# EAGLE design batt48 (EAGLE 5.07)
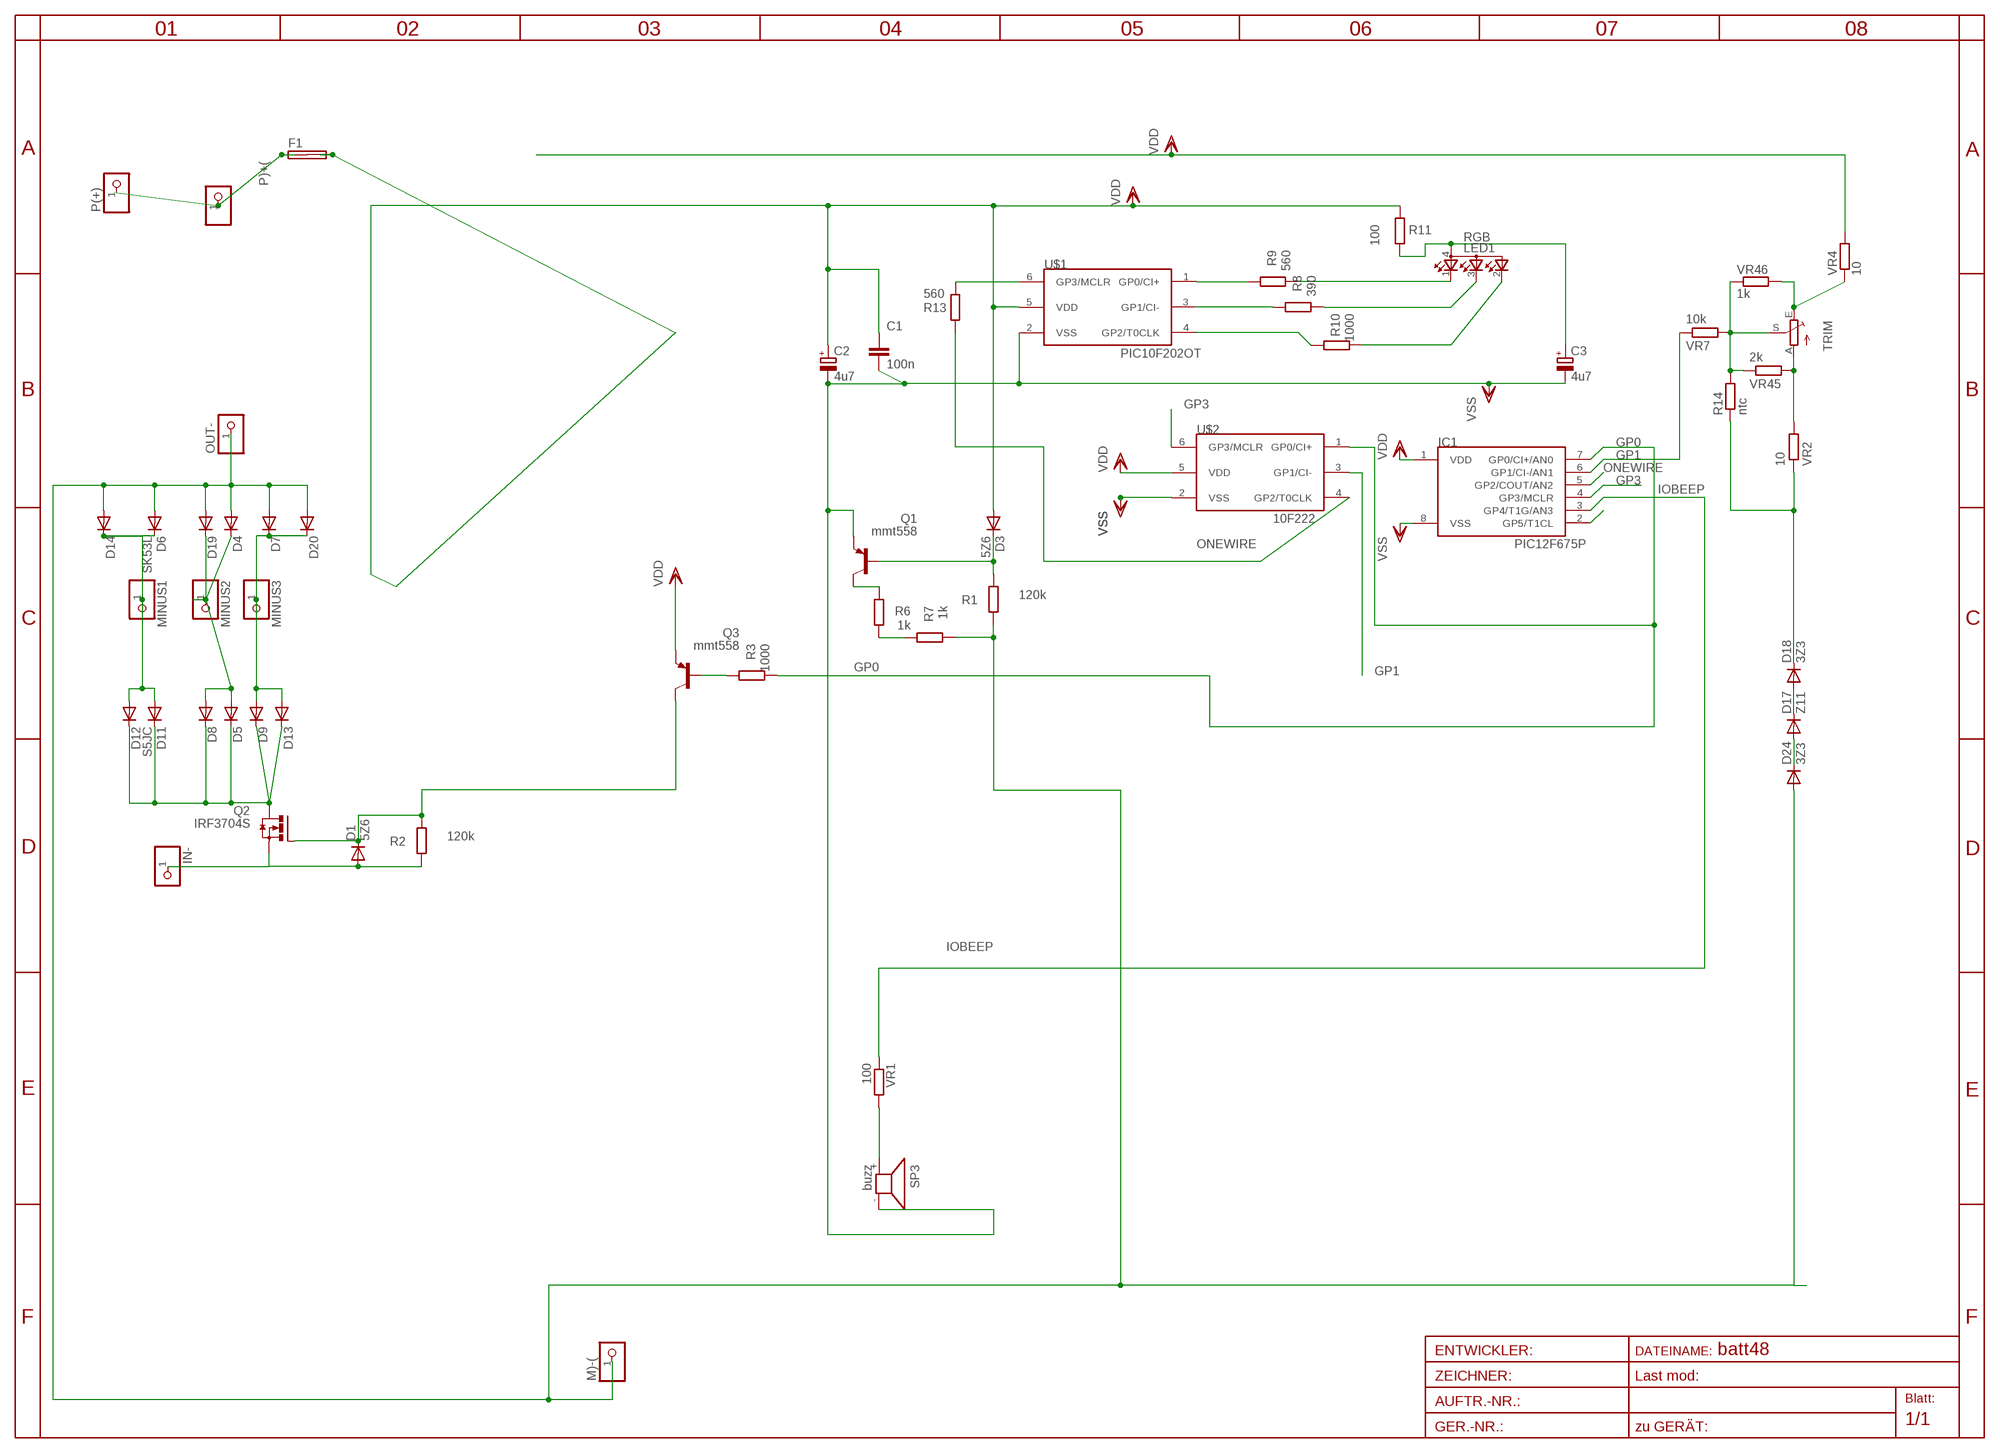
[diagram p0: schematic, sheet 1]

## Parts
C1  100n  C-EUC1206  [C1206]
C2  4u7  CPOL-EUSMCA  [SMC_A]
C3  4u7  CPOL-EUSMCA  [SMC_A]
D1  5Z6  DIODE-MINIMELF  [MINIMELF]
D3  5Z6  DIODE-MINIMELF  [MINIMELF]
D4  DIODE-SMC  [SMC]
D5  DIODE-SMC  [SMC]
D6  SK53L  DIODE-SMC  [SMC]
D7  DIODE-SMC  [SMC]
D8  DIODE-SMC  [SMC]
D9  DIODE-SMC  [SMC]
D11  S5JC  DIODE-SMC  [SMC]
D12  DIODE-SMC  [SMC]
D13  DIODE-SMC  [SMC]
D14  DIODE-SMC  [SMC]
D17  Z11  DIODE-MINIMELF  [MINIMELF]
D18  3Z3  DIODE-MINIMELF  [MINIMELF]
D19  DIODE-SMC  [SMC]
D20  DIODE-SMC  [SMC]
D24  3Z3  DIODE-MINIMELF  [MINIMELF]
F1  SHK20L7MM5  [7MM5]
IC1  PIC12F675P  [DIL8]
IN-  PINHD-1X12MM3  [1X2MM3]
LED1  RGB  GM1WA55311A  [FULL3528]
M)-(  PINHD-1X11X0.4  [1X01]
MINUS1  PINHD-1X12MM3  [1X2MM3]
MINUS2  PINHD-1X12MM3  [1X2MM3]
MINUS3  PINHD-1X12MM3  [1X2MM3]
OUT-  PINHD-1X12MM3  [1X2MM3]
P(+)  PINHD-1X14.5MM  [1X4MM5]
P)+(  PINHD-1X11X0.4  [1X01]
Q1  mmt558  BC857ALT1SMD  [SOT23-BEC]
Q2  IRF3704S  [D2PACK]
Q3  mmt558  BC857ALT1SMD  [SOT23-BEC]
R1  120k  R-EU_R1206  [R1206]
R2  120k  R-EU_R0805  [R0805]
R3  1000  R-EU_R0805  [R0805]
R6  1k  R-EU_R1206  [R1206]
R7  1k  R-EU_R1206  [R1206]
R8  390  R-EU_R0805  [R0805]
R9  560  R-EU_R0805  [R0805]
R10  1000  R-EU_R0805  [R0805]
R11  100  R-EU_R1206  [R1206]
R13  560  R-EU_R0805  [R0805]
R14  ntc  R-EU_0204/5  [0204/5]
SP3  buzz  KSS12017MM  [KSS1202]
TRIM  TRIM_EU-S64W  [S64W]
U$1  PIC10F202OT  [SOT23-6]
U$2  10F222  PIC10F204OT  [SOT23-6]
VR1  100  R-EU_R0805  [R0805]
VR2  10  R-EU_R0805  [R0805]
VR4  10  R-EU_R1206  [R1206]
VR7  10k  R-EU_R0805  [R0805]
VR45  2k  R-EU_R0805  [R0805]
VR46  1k  R-EU_R0805  [R0805]

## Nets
A: C3.+ LED1.4(A) R11.1
B: LED1.3(CBLUE) R8.1
B1: D6.C D11.A D12.A D14.C MINUS1.1
B2: D7.C D9.A D13.A D20.C MINUS3.1
B3: D4.C D5.A D8.A D19.C MINUS2.1
BUZZ+: SP3.+ VR1.2
G: LED1.2(CGREEN) R10.1
GP0: IC1.7(GP0/CI+/AN0) R3.1 U$2.1(GP0/CI+)
GP0C: R9.2 U$1.1(GP0/CI+)
GP1: IC1.6(GP1/CI-/AN1) U$2.3(GP1/CI-) VR7.1
GP1C: R8.2 U$1.3(GP1/CI-)
GP2C: R10.2 U$1.4(GP2/T0CLK)
GP3: IC1.4(GP3/MCLR) U$2.6(GP3/MCLR)
GP3_2: R13.1 U$1.6(GP3/MCLR)
IN+: F1.1A F1.1B P(+).1 P)+(.1
IN-: D5.C D8.C D9.C D11.C D12.C D13.C Q2.2(D)
IOBEEP: IC1.3(GP4/T1G/AN3) VR1.1
N$1: D1.A IN-.1 Q2.3(S) R2.2
N$2: D3.C Q1.B R1.1
N$4: D1.C Q2.1(G) Q3.C R2.1
N$5: D18.C R14.1 VR2.1
N$6: Q1.C R6.2
N$7: TRIM.A VR2.2 VR45.2
N$8: Q3.B R3.2
N$12: D17.C D18.A
N$14: D17.A D24.C
N$18: R6.1 R7.2
N$22: R14.2 TRIM.S VR7.2 VR45.1 VR46.1
N$24: TRIM.E VR4.1 VR46.2
N$38: IC1.2(GP5/T1CL)
ONEWIRE: IC1.5(GP2/COUT/AN2) R13.2 U$2.4(GP2/T0CLK)
OUT-: D4.A D6.A D7.A D14.A D19.A D20.A D24.A M)-(.1 OUT-.1 R1.2 R7.1
R: LED1.1(CRED) R9.1
VDD: C1.1 C2.+ D3.A F1.2A F1.2B IC1.1(VDD) Q3.E R11.2 U$1.5(VDD) U$2.5(VDD) VR4.2
VSS: C1.2 C2.- C3.- IC1.8(VSS) Q1.E SP3.- U$1.2(VSS) U$2.2(VSS)

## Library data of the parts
C1 = rcl:C-EU: CAPACITOR, European symbol
C2 C3 = rcl:CPOL-EU: POLARIZED CAPACITOR, European symbol
D1 D3-D9 D11-D14 D17-D20 D24 = diode:DIODE-: DIODE
F1 = fuse:SHK20L: FUSE HOLDER 5 x 20 mm, SH contact, SHH1 Schukat, E1073 Buerklin
IC1 = microchip-3:PIC12F6*: uPC nW 1k Program Flash memory 2x Timer Comparator 10b A/D converter/ 4xIN
IN- M)-( MINUS1-MINUS3 OUT- P(+) P)+( = pinhead:PINHD-1X1: PIN HEADER
LED1 = led:GM1WA55311A: Chip LED RGB Source: http://document.sharpsma.com/files/GM1WA55311A_SS.pdf
Q1 Q3 = transistor-pnp:BC857*: PNP Transistror
Q2 = transistor-power:IRF3704: SMPS MOSFET HEXFET® Power MOSFET Source: http://www.irf.com/product-info/datasheets/data/irf3704.pdf
R1-R3 R6-R11 R13 VR1 VR2 VR4 VR7 VR45 VR46 = rcl-2:R-EU_: RESISTOR, European symbol
R14 = rcl:R-EU_: RESISTOR, European symbol
SP3 = buzzer:KSS1201: SPEAKER
TRIM = pot:TRIM_EU-: POTENTIOMETER
U$1 U$2 = microchip-3:PIC10F2*: uPC nW 0,25/0,5k Program Flash memory Comparator

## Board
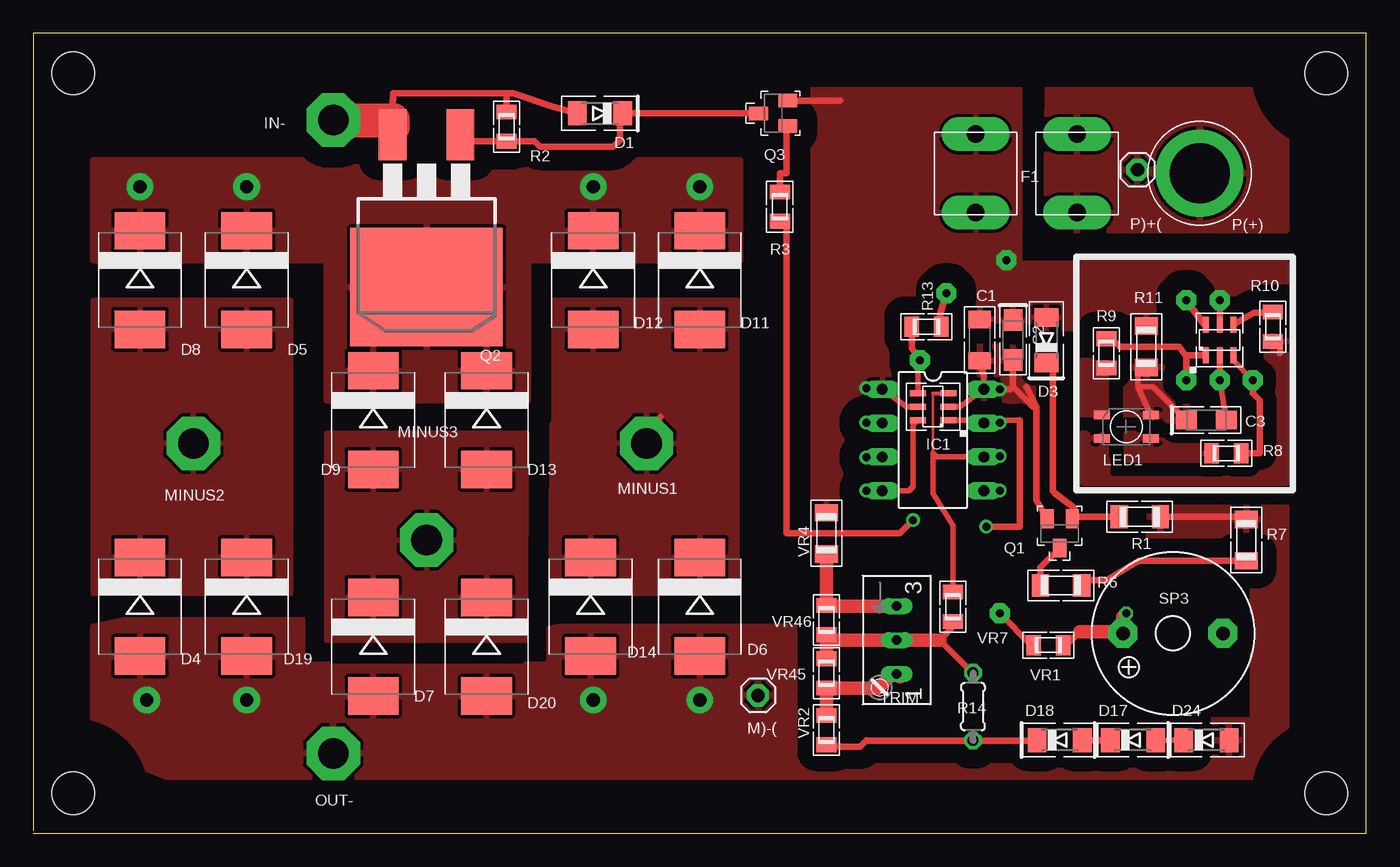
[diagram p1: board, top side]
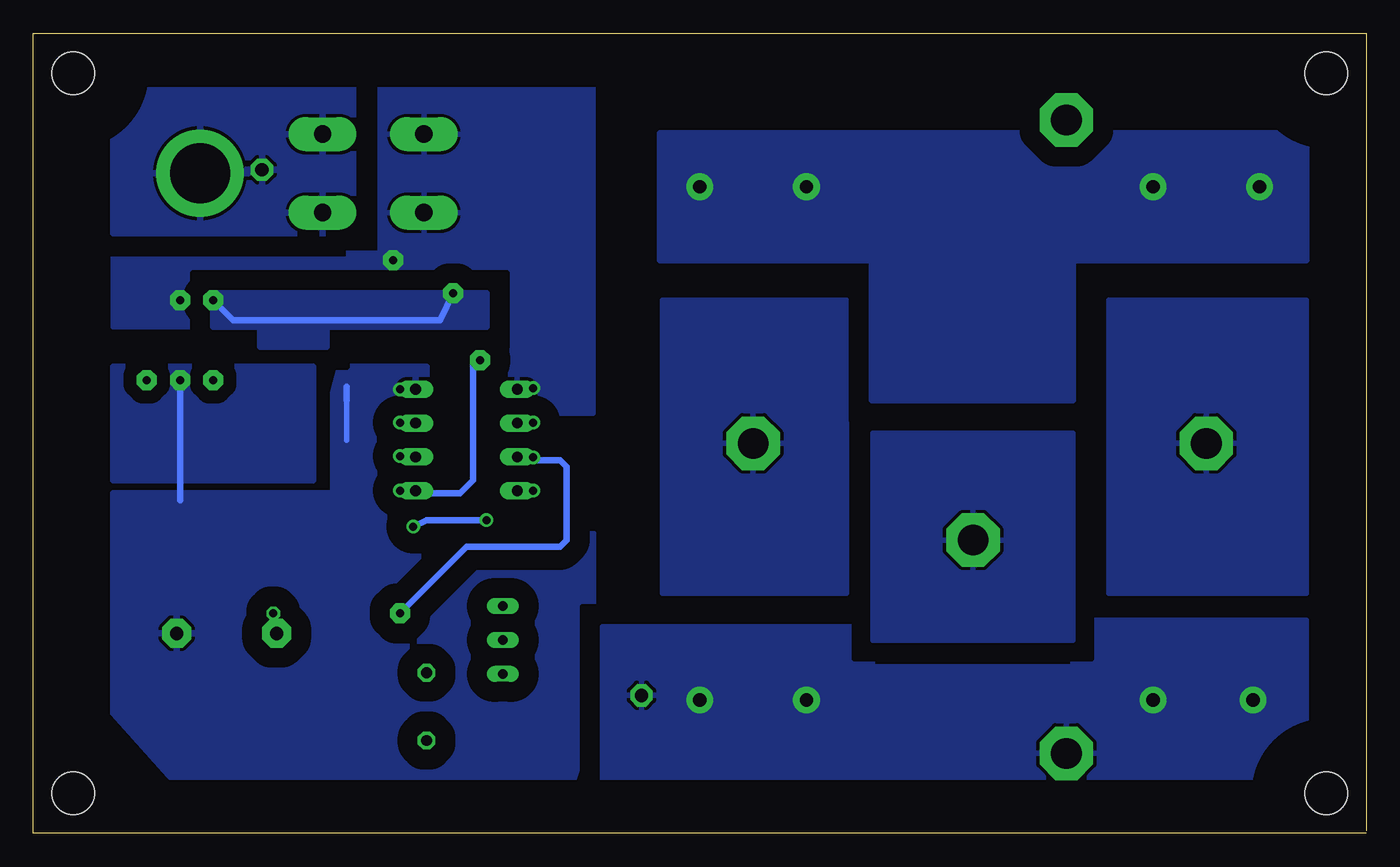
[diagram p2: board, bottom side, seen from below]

Size 100 x 60 mm. Coordinates in mm from the lower left corner, seen from the top.
Outline: 0,0 100,0 100,60 0,60 0,0.2
Copper layers (1*16): Top 0.035mm / dielectric 1.5mm / Bottom 0.035mm
Design rules "default *": minimum track width 8mil, minimum drill 4mil, track to track 8mil, track to pad 8mil, pad to pad 8mil, via to via 8mil, smd to smd 8mil, copper to edge 4mm, drill to drill 8mil, minimum pad ring 10mil, minimum via ring 8mil, stop-mask expansion 4mil, vias tented up to drill 0mil, thermal gap 10mil
Holes 3.2 mm at 3,57 3,3 97,57 97,3

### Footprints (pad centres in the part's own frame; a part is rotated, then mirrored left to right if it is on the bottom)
C1206 = smd 1.3 x 1.7: 1 -1.55,0; 2 1.55,0
SMC_A = smd 1.6 x 1.4: + -1.5,0; - 1.5,0
MINIMELF = smd 1.4 x 1.8: A 1.7,0; C -1.7,0
SMC = smd 2.8 x 3.8: A 3.7,0; C -3.7,0
7MM5 = drill 1.3 pad 2.54 long: 1A -3.8,2.94; 1B -3.8,-2.94; 2A 3.8,2.94; 2B 3.8,-2.94
DIL8 = drill 0.813 long: 1 -3.81,-3.81; 2 -1.27,-3.81; 3 1.27,-3.81; 4 3.81,-3.81; 5 3.81,3.81; 6 1.27,3.81; 7 -1.27,3.81; 8 -3.81,3.81
1X2MM3 = drill 2.3 pad 4 octagon: 1 0,0
FULL3528 = smd 0.65 x 1.2: 1 0.875,1.85; 2 -0.875,1.85; 3 -0.875,-1.85; 4 0.875,-1.85
1X01 = drill 1 pad 1.676 octagon: 1 0,0
1X4MM5 = drill 4.5 pad 6.35 round: 1 0,0
SOT23-BEC = smd 1 x 1.4: B -0.95,-1.1; C 0,1.1; E 0.95,-1.1
D2PACK = smd 2.083 x 3.81: 1 -2.54,-8.89; 3 2.54,-8.89 | smd 11.43 x 8.89: 2 0,2.54
R1206 = smd 1.3 x 1.7: 1 -1.55,0; 2 1.55,0
R0805 = smd 1.1 x 1.5: 1 -1.1,0; 2 1.1,0
0204/5 = drill 0.813 octagon: 1 -2.54,0; 2 2.54,0
KSS1202 = drill 1 pad 2.159 octagon: + 3.75,0; - -3.75,0
S64W = drill 0.7 long: A 2.54,1.27; E -2.54,1.27; S 0,1.27
SOT23-6 = smd 0.45 x 1.2: 1 -1.016,-1.15; 2 0,-1.15; 3 1.016,-1.15; 4 1.016,1.15; 5 0,1.15; 6 -1.016,1.15

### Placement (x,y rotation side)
C1  71,37 270 top
C2  73.5,37 270 top
C3  88,31 0 top
D1  42.5,54 180 top
D3  76,37 90 top
D4  8,17 270 top
D5  16,41.5 270 top
D6  50,17 270 top
D7  25.5,14 270 top
D8  8,41.5 270 top
D9  25.5,31 270 top
D11  50,41.5 270 top
D12  42,41.5 270 top
D13  34,31 270 top
D14  41.8,17 270 top
D17  82.5,7 0 top
D18  77,7 0 top
D19  16,17 270 top
D20  34,14 270 top
D24  88,7 0 top
F1  74.5,49.5 180 top
IC1  67.5,29.5 270 top
IN-  22.5,53.5 180 top
LED1  82,30.5 90 top
M)-(  54.37,10.35 0 top
MINUS1  46,29.25 180 top
MINUS2  12,29.25 180 top
MINUS3  29.5,22 180 top
OUT-  22.5,6 180 top
P(+)  87.5,49.5 0 top
P)+(  82.84,49.77 0 top
Q1  77,22.5 180 top
Q2  29.5,43.5 180 top
Q3  55.5,54 90 top
R1  83,23.75 0 top
R2  35.5,53 90 top
R3  56,47 90 top
R6  77.1,18.6 180 top
R7  91,22 270 top
R8  89.5,28.5 0 top
R9  80.5,36 90 top
R10  93,38 90 top
R11  83.5,36.5 90 top
R13  67,38 180 top
R14  70.5,9.5 90 top
SP3  85.5,15 180 top
TRIM  63.5,14.5 270 top
U$1  89,37 0 top
U$2  67.5,32 90 top
VR1  76.16,14.11 0 top
VR2  59.5,7.75 90 top
VR4  59.5,22.5 90 top
VR7  69,17 270 top
VR45  59.5,12 270 top
VR46  59.5,16 90 top

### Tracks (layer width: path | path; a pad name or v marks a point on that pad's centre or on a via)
A
  Top 0.4: 82.85,33.5 82.85,34.8 R11.1 | LED1.4 82.85,33.5 | C3.+ 84,33.5 82.85,33.5
  pour Top (isolate 1, rank 2): 82,35.5 87,35.5 87,31 82,31
B
  pour Top (isolate 1.016): 82,30 83.5,30 84,29.5 88,29.5 88,28 82,28
B1
  Top 0.5: MINUS1.1 47.05,31.25
  pour Top (isolate 1.5, rank 4): 52.8,18 38.8,18 38.8,40 52.8,40
  pour Bottom (isolate 1.5, rank 4): 52.8,18 39,18 39,40 52.8,40
B2
  pour Top (isolate 1.5, rank 3): 22,14.5 22,30 37,30 36.9,14.5
  pour Bottom (isolate 1.5, rank 3): 22,14.5 22,30 37,30 37,14.5
B3
  pour Top (isolate 1.5, rank 4): 4.5,18 4.5,40 19.3,40 19.3,18
  pour Bottom (isolate 1.5, rank 4): 4.5,18 4.5,40 19.3,40 19.3,18
BUZZ+  (via drill 0.6)
  Top 0.406: 81.75,16.25 v82,16.5 81.39,15.11
  Top 0.5: VR1.2 77.5,14.11 78.5,15.11
  Top 1: 81.75,16.25 SP3.+ | 78.5,15.11 81.39,15.11
G
  Top 0.5: R10.1 93.5,36.9 93.5,36
  pour Top (isolate 1, rank 2): 78.75,30 80.5,30 80.5,28 92.5,28 92.5,37.5 94,37.5 94,26.25 78.75,26.25
GP0  (via drill 0.6 pad 0.81, 0.6 pad 1)
  Top 0.4: U$2.1 71.1,30.98 IC1.7
  Top 0.406: 74,31 71.5,31 71.31,30.81 IC1.7 71.34,30.8 v72.5,30.8
  Top 0.5: R3.1 56.5,45.9 56.5,22.5 65,22.5 v66,23.5 | v71.5,23 74,23 74,31
  Bottom 0.5: v66,23.5 70.5,23.5 v71.5,23
GP0C  (via drill 0.6 pad 1.5)
  Top 0.4: R9.2 80.9,37.1 81.5,36.5
  Top 0.5: 86.5,35.75 v86.5,34 | 81.5,36.5 85.97,36.5 86.5,35.75 | U$1.1 86.6,35.85 86.5,35.75
GP1  (via drill 0.6 pad 1)
  Top 0.2: 67.5,28.5 67.5,33
  Top 0.3: 67.5,33 68.63,33
  Top 0.4: IC1.6 67.77,28.23 67.5,28.5 67.5,25.5 69,23.1
  Top 0.406: VR7.1 69,23.1 | IC1.6 72.43,28.23 v72.5,28.3 | 68.63,33 U$2.3
GP1C  (via drill 0.6 pad 1.5)
  Top 0.4: U$1.3 90.02,35.48 v91.5,34
  Top 0.5: v91.5,34 91.5,33 92,32.5 92,28.5 R8.2
GP2C
  Top 0.5: U$1.4 91.55,39.05 93,39.05 R10.2
GP3  (via drill 0.6 pad 1)
  Top 0.4: IC1.4 65.69,25.69 66,26 66,30.63 U$2.6
  Top 0.406: IC1.4 v62.51,25.69 v62.5,25.7
GP3_2  (via drill 0.6 pad 1.5)
  Top 0.5: U$1.6 87.85,38.15 v86.5,40 | v68.5,40.5 68,38.9 R13.1
  Bottom 0.5: v86.5,40 85,38.5 69.5,38.5 v68.5,40.5
  pour Bottom (isolate 1): 66,40.5 86.5,40.5 86.5,38 83,38 83,36.5 78,36.5 78,38 66,38
IN+
  pour Top (isolate 1.5): 76.1,56 94,56 94,45.25 77,45.25 76,46
  pour Bottom (isolate 1.5): 76,56 94,56 94,45 77,45 76,46
IN-  (via drill 1 pad 2)
  other vias: 8,48.5 16,48.5 42,48.5 50,48.5
  pour Top (isolate 1.5): 4.5,50.5 53,50.5 53,43 37.1,43 37.1,32.5 22,32.5 22,43 4.5,43
  pour Bottom (isolate 1.5): 4.5,52.5 53,52.5 53,43 37.1,43 37.1,32.5 22,32.5 22,43 4.5,43
IOBEEP  (via drill 0.6 pad 1, 0.6 pad 1.5)
  Top 0.406: v62.5,28.2 62.7,28
  Top 0.5: VR1.1 74.89,14.11 v72.5,16.5
  Bottom 0.406: v72.5,16.5 72,16.5 | 63.46,28 IC1.3
  Bottom 0.5: 62.5,28 60.5,28 60,27.5 60,22 60.5,21.5 67.5,21.5 v72.5,16.5 | 62.5,28 63.46,28 | 62.5,28 v62.5,28.2
N$1
  Top 0.5: D1.A 39,54.5 36,55.5 35.5,55.5 | 35.5,55.5 27,55.5 27,55 26.96,55 26.96,53 Q2.3 | 35.5,55.5 R2.2
  Top 2.54: IN-.1 26.96,53.5 26.96,53
N$2
  Top 0.5: D3.C 76.22,35.28 76.5,35 76.5,25.65 76.65,25.5 78,24.5 78.1,24.4 78.1,23.75 | 78.1,23.75 R1.1 | Q1.B 78.1,23.75
N$3  (via drill 0.6 pad 1)
  other vias: 72.5,25.7
N$4
  Top 0.5: Q3.C D1.C 44,53.8 44,52 43.5,51.5 38,51.5 37.6,51.9 R2.1 32.9,51.9 32.5,51.5 32,51.5 Q2.1
N$5
  Top 0.5: VR2.1 60.6,6.5 62,6.5 62.5,7 62.5,6.96 R14.1 75.26,6.96 D18.C
N$6
  Top 0.5: R6.2 75.55,19.95 Q1.C
N$7
  Top 0.406: 65,11.73 TRIM.A
  Top 0.5: VR2.2 60,9 59.5,9
  Top 1: 65,11.73 64.5,12 63.4,10.9 VR45.2 59.5,9
N$8
  Top 0.5: Q3.B 56.5,53.05 56.5,49.5 56,49.5 R3.2
N$12
  Top 0.5: D18.A D17.C
N$14
  Top 0.406: D24.C D17.A
N$18
  Top 0.5: R7.2 82.95,20.45 80.5,19 79.05,19 R6.1
N$22
  Top 0.406: 69,15.5 VR7.2
  Top 0.5: 69,15.5 68,14.5 70.46,12.04 R14.2
  Top 1: VR46.1 59.5,14.5 | VR45.1 59.5,14 59.5,14.5 | 68,14.5 TRIM.S 59.5,14.5
N$24
  Top 0.406: VR46.2 59.94,17.04
  Top 1: 59.94,17.04 TRIM.E | VR46.2 VR4.1
N$29  (via drill 0.6 pad 1)
  other vias: 62.5,30.8
ONEWIRE  (via drill 0.6 pad 1.5)
  Top 0.4: U$2.4 66.35,34.5 66.35,34.85
  Top 0.406: v66.5,35.5 66.35,35.85 66.35,34.5
  Top 0.5: R13.2 65.9,36.4 v66.5,35.5
  Bottom 0.406: 67,35.5 v66.5,35.5 | 71.12,25.5 IC1.5
  Bottom 0.5: 71.12,25.5 68,25.5 67,26.5 67,35.5
OUT-  (via drill 1 pad 2)
  Top 0.406: 91,23.75 R7.1
  Top 0.5: R1.2 91,23.75
  other vias: 50,10 42,10 16,10 8.5,10
  pour Top (isolate 1.422, rank 5): 94,3.5 11.8,3.5 4.5,6.5 4.5,15.5 6.8,16 21.5,16 22,12.5 37,12.5 37,15 39.5,15.5 69,15.5 69,8.5 91.5,8.5 91.5,21 83.5,21 83.5,24.5 94,24.5
  pour Bottom (isolate 1.422, rank 4): 57.3,4 8.3,3.5 4.5,6.5 4.5,16 22,16 22,12.5 37,12.5 37.5,15.5 57.3,15.5
R
  pour Top (isolate 1, rank 3, no thermals): 78.75,35.5 80.5,35.5 80.5,31 78.75,31
VDD  (via drill 0.6 pad 1, 0.6 pad 1.5)
  Top 0.4: U$2.5 65.5,32 IC1.1 63.5,33.5
  Top 0.406: 63.5,33.5 62.6,33.5 v62.5,33.4
  Top 0.5: U$1.5 v89,40 | Q3.E 60.5,54.95 60.5,55
  other vias: 73,43
  pour Top (isolate 1.5, rank 2): 74,42.75 74,56 58.5,56 58.5,23.5 64,23.5 64,26 64.5,33.5 65,34 69,38.5 70,38 94,37.5 94,42.75
  pour Bottom (isolate 1.5, rank 2): 74,43.5 74,56 58,56 58,31.5 64.5,31.5 64.5,33.5 65,34 69,38.5 70,38 94,38 94,43.5
VSS  (via drill 0.6 pad 1, 0.6 pad 1.5)
  Top 0.4: v89,34 C3.- | U$2.2 69.5,32
  Top 0.406: SP3.- 89.25,15.75 | 69.5,32 IC1.8 71.31,34.26
  Top 0.5: v89,34 U$1.2 | 71.31,34.26 C1.2 | Q1.E 75.25,25 75.25,32 | 75.25,32 74.5,33.5 | 75.25,32 75,32 73.5,33.5 | 73.5,33.5 C2.- | v72.5,33.3 73.3,33.3 73.5,33.5
  Bottom 0.406: 76.5,29.5 76.5,32.5
  Bottom 0.5: 89,25 v89,34 | 76.5,32.5 76.5,33.5
  pour Bottom (isolate 1.5, rank 5): 70.5,35 77,35 77.5,33 77.5,25.5 94,25.5 94,9 89.5,4 59.5,4 58,8.5 58,22.5 71,22.5 73.5,25 73.5,30.5 71,30.5 70.5,31
  pour Top (isolate 1): 70.5,36.5 75.5,36.5 75.5,32 70.5,32 70.5,35
  pour Bottom (isolate 1, rank 5): 79,35 94,35 94,26.5 79,26.5

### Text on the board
tTest: 4v4
Document: 1m | 10u | 10u | 300u | 2mA | 500u | 1m | 2m | 300u | 300u | 30u | 5m | 14m | 12m | 500u | 5m | 5m | 5m | 5m | 5m | 5m | 40m | 40m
